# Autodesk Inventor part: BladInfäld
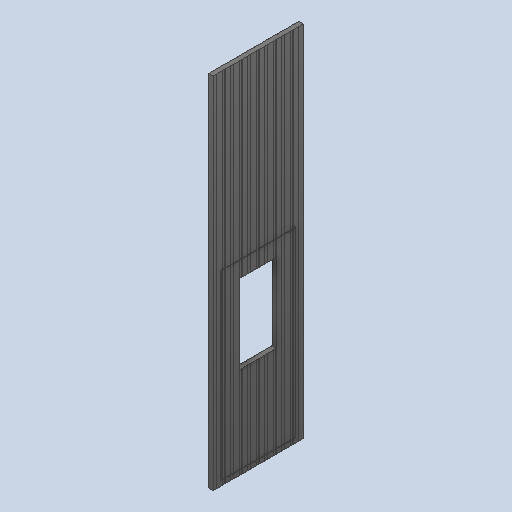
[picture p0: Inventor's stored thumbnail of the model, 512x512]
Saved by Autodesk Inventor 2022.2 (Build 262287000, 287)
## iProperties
Created: 2019-06
Part Number: BladInfäld
Material: UHMW, Black
Document SubType Name: Modeling
Designer: cl
Density: 0.94 g/cm^3
Appearance: Smooth - Black
Author: cl
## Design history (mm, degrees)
sketch "Sketch4"
  geometry: L1 (0, 0)-(0, -35); L2 (0, -35)-(1.4, -36.4); L3 (1.4, -36.4)-(1.4, -96.4); L4 (1.4, -96.4)-(0, -97.8); L5 (0, 0)-(-23.6, 0); L6 (0, -97.8)-(-23.6, -97.8); L7 (-23.6, -97.8)-(-23.6, 0); L8 (-47.2, 0)-(-23.6, 0); L9 (-47.2, 0)-(-47.2, -35); L10 (-47.2, -35)-(-48.6, -36.4); L11 (-48.6, -36.4)-(-48.6, -96.4); L12 (-48.6, -96.4)-(-47.2, -97.8); L13 (-47.2, -97.8)-(-23.6, -97.8); 1 further point
  constraints: 26 end point, 5 symmetric about line, 3 vertical, 2 horizontal, 1 coincident
  dimensions: "d41" = 35 distance of L1.start L1.end; "d43" = 45 deg angle of L2 L1; "d44" = 60 distance of L2.end L3.end; "d45" = 45 deg angle of L3 L4; "d46" = 1.4 distance between parallel lines of L1 L3; "d47" = 1.4 horizontal distance of L3.end L4.end (derived); "d48" = 23.6 distance of L1.start L5.end
extrude "Extrusion2" new body sketch "Sketch4" distance "d49" = 3921 (derived); taper "d50" = 0 deg
sketch "Sketch5"
  geometry: L1 (-48.6, -96.4)-(-47.2, -97.8) reference; L2 (-47.2, -97.8)-(-47.2, -127.8); L3 (-47.2, -97.8)-(-17.2, -97.8); L4 (-47.2, -127.8)-(-48.6, -129.2); L5 (-48.6, -129.2)-(-48.6, -189.2); L6 (-47.2, -97.8)-(-23.6, -97.8); L7 (-47.2, -97.8)-(0, -97.8) reference; L8 (-23.6, -97.8)-(-23.6, -190.6); L9 (-48.6, -189.2)-(-47.2, -190.6); L10 (-47.2, -190.6)-(-23.6, -190.6); L11 (0, -97.8)-(-30, -97.8); L12 (0, -97.8)-(0, -127.8); L13 (0, -127.8)-(1.4, -129.2); L14 (1.4, -129.2)-(1.4, -189.2); L15 (0, -190.6)-(-23.6, -190.6); L16 (1.4, -189.2)-(0, -190.6); 1 further point
  constraints: 28 end point, 5 symmetric about line, 2 horizontal, 2 perpendicular, 2 vertical, 1 midpoint, 1 parallel
  dimensions: "d51" = 30 distance of L1.end L2.end; "d52" = 90 deg angle of L2 L3 (derived); "d54" = 1.4 distance between parallel lines of L2 L5; "d55" = 23.6 distance of L1.end L6.end; "d56" = 45 deg angle of L9 L5; "d57" = 1.4 distance from line of L5 L9.end; "d60" = 60 distance of L4.end L5.end
extrude "Extrusion3" join sketch "Sketch5" distance "d58" = 3921 (derived); taper "d59" = 0 deg
pattern_linear "Rectangular Pattern1" dims "d61" = 85.33405 (derived), "d63" = 92.8
sketch "Sketch7"
  geometry: L1 (-47.2, -189.233)-(0, -189.233); L2 (0, -189.233)-(0, -983.5); L3 (0, -983.5)-(-47.2, -983.5); L4 (-47.2, -983.5)-(-47.2, -189.233); L5 (0, 0)-(-47.2, 0) reference; L6 (-47.2, -97.8)-(-47.2, -127.8) reference; L7 (-47.2, -127.8)-(-48.6, -129.2) reference; L8 (-48.6, -129.2)-(-48.6, -189.2) reference; L9 (-48.6, -189.2)-(-47.2, -190.6) reference; L10 (-47.2, -190.6)-(-47.2, -220.6) reference; L11 (-47.2, -220.6)-(-48.6, -222) reference; L12 (-48.6, -222)-(-48.6, -282) reference; L13 (-48.6, -282)-(-47.2, -283.4) reference; L14 (-47.2, -283.4)-(-47.2, -313.4) reference; L15 (-47.2, -313.4)-(-48.6, -314.8) reference; L16 (-48.6, -314.8)-(-48.6, -374.8) reference; L17 (-48.6, -374.8)-(-47.2, -376.2) reference; L18 (0, -376.2)-(1.4, -374.8) reference; L19 (1.4, -374.8)-(1.4, -314.8) reference; L20 (1.4, -314.8)-(0, -313.4) reference; L21 (0, -313.4)-(0, -283.4) reference; L22 (0, -283.4)-(1.4, -282) reference; L23 (1.4, -282)-(1.4, -222) reference; L24 (1.4, -222)-(0, -220.6) reference; L25 (0, -220.6)-(0, -190.6) reference; L26 (0, -190.6)-(1.4, -189.2) reference; L27 (1.4, -189.2)-(1.4, -129.2) reference; L28 (1.4, -129.2)-(0, -127.8) reference; L29 (0, -127.8)-(0, -97.8) reference; L30 (-47.2, -35)-(-48.6, -36.4) reference; L31 (-48.6, -36.4)-(-48.6, -96.4) reference; L32 (-48.6, -96.4)-(-47.2, -97.8) reference; L33 (0, -97.8)-(1.4, -96.4) reference; L34 (1.4, -96.4)-(1.4, -36.4) reference; L35 (1.4, -36.4)-(0, -35) reference; L36 (0, -35)-(0, 0) reference; L37 (0, 0)-(-47.2, 0) reference; L38 (-47.2, 0)-(-47.2, -35) reference; L39 (-47.2, -376.2)-(-47.2, -406.2) reference; L40 (-47.2, -406.2)-(-48.6, -407.6) reference; L41 (-48.6, -407.6)-(-48.6, -467.6) reference; L42 (-48.6, -467.6)-(-47.2, -469) reference; L43 (-47.2, -469)-(-47.2, -499) reference; L44 (-47.2, -499)-(-48.6, -500.4) reference; L45 (-48.6, -500.4)-(-48.6, -560.4) reference; L46 (-48.6, -560.4)-(-47.2, -561.8) reference; L47 (0, -561.8)-(1.4, -560.4) reference; L48 (1.4, -560.4)-(1.4, -500.4) reference; L49 (1.4, -500.4)-(0, -499) reference; L50 (0, -499)-(0, -469) reference; L51 (0, -469)-(1.4, -467.6) reference; L52 (1.4, -467.6)-(1.4, -407.6) reference; L53 (1.4, -407.6)-(0, -406.2) reference; L54 (0, -406.2)-(0, -376.2) reference; L55 (-47.2, -561.8)-(-47.2, -591.8) reference; L56 (-47.2, -591.8)-(-48.6, -593.2) reference; L57 (-48.6, -593.2)-(-48.6, -653.2) reference; L58 (-48.6, -653.2)-(-47.2, -654.6) reference; L59 (-47.2, -654.6)-(-47.2, -684.6) reference; L60 (-47.2, -684.6)-(-48.6, -686) reference; L61 (-48.6, -686)-(-48.6, -746) reference; L62 (-48.6, -746)-(-47.2, -747.4) reference; L63 (0, -747.4)-(1.4, -746) reference; L64 (1.4, -746)-(1.4, -686) reference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; 2 further points
  constraints: 8 end point, 2 parallel, 2 point on line, 1 horizontal, 1 perpendicular
  dimensions: "d67" = 983.5 distance between parallel lines of L5 L3 (derived); "d103" = 47.2 distance between parallel lines of L2 L4
extrude "Extrusion5" join sketch "Sketch7" distance "d68" = 3921 (derived); taper "d69" = 0 deg
sketch "Sketch10"
  geometry: L1 (195.35, 1862)-(595.35, 1862); L2 (595.35, 1862)-(595.35, 1000); L3 (595.35, 1000)-(195.35, 1000); L4 (195.35, 1000)-(195.35, 1862); L5 (395.35, 1000)-(395.35, 1862); L6 (195.35, 1000)-(595.35, 1000); L7 (595.35, 1000)-(595.35, 1862); L8 (595.35, 1862)-(195.35, 1862); L9 (195.35, 1862)-(195.35, 1000); L10 (395.35, 1862)-(395.35, 1000); 1 further point
  constraints: 20 end point, 4 midpoint, 4 parallel, 2 horizontal, 2 perpendicular, 1 collinear
  dimensions: "d82" = 862 distance of L1.end L2.end (derived); "d83" = 400 distance of L2.end L3.end (derived); "d86" = 491.75 distance from line of L5 point (-96.4, 0) (derived); "d92" = 1000 distance from line of point (-96.4, 0) L3 (derived); "d93" = 400 distance of L6.start L6.end (derived); "d94" = 862 distance of L6.end L7.end (derived); "d95" = 0.0001 distance between parallel lines of L3 L6 (derived)
extrude "Extrusion8" cut sketch "Sketch10" stored distance "d87" = 100; taper "d88" = 0 deg
sketch "Sketch13"
  geometry: L1 (-35, 0)-(-35, 3921) reference; L2 (711, 0)-(712.4, 0) reference; L3 (651, 0)-(711, 0) reference; L4 (649.6, 0)-(651, 0) reference; L5 (619.6, 0)-(649.6, 0) reference; L6 (618.2, 0)-(619.6, 0) reference; L7 (558.2, 0)-(618.2, 0) reference; L8 (556.8, 0)-(558.2, 0) reference; L9 (526.8, 0)-(556.8, 0) reference; L10 (525.4, 0)-(526.8, 0) reference; L11 (465.4, 0)-(525.4, 0) reference; L12 (464, 0)-(465.4, 0) reference; L13 (434, 0)-(464, 0) reference; L14 (432.6, 0)-(434, 0) reference; L15 (372.6, 0)-(432.6, 0) reference; L16 (371.2, 0)-(372.6, 0) reference; L17 (341.2, 0)-(371.2, 0) reference; L18 (339.8, 0)-(341.2, 0) reference; L19 (279.8, 0)-(339.8, 0) reference; L20 (278.4, 0)-(279.8, 0) reference; L21 (248.4, 0)-(278.4, 0) reference; L22 (247, 0)-(248.4, 0) reference; L23 (187, 0)-(247, 0) reference; L24 (185.6, 0)-(187, 0) reference; L25 (155.6, 0)-(185.6, 0) reference; L26 (154.2, 0)-(155.6, 0) reference; L27 (94.2, 0)-(154.2, 0) reference; L28 (92.8, 0)-(94.2, 0) reference; L29 (62.8, 0)-(92.8, 0) reference; L30 (61.4, 0)-(62.8, 0) reference; L31 (1.4, 0)-(61.4, 0) reference; L32 (0, 0)-(1.4, 0) reference; L33 (-35, 0)-(0, 0) reference; L34 (0, 0)-(-35, 0) reference; L35 (1.4, 0)-(0, 0) reference; L36 (61.4, 0)-(1.4, 0) reference; L37 (62.8, 0)-(61.4, 0) reference; L38 (92.8, 0)-(62.8, 0) reference; L39 (94.2, 0)-(92.8, 0) reference; L40 (154.2, 0)-(94.2, 0) reference; L41 (155.6, 0)-(154.2, 0) reference; L42 (185.6, 0)-(155.6, 0) reference; L43 (187, 0)-(185.6, 0) reference; L44 (247, 0)-(187, 0) reference; L45 (248.4, 0)-(247, 0) reference; L46 (278.4, 0)-(248.4, 0) reference; L47 (279.8, 0)-(278.4, 0) reference; L48 (339.8, 0)-(279.8, 0) reference; L49 (341.2, 0)-(339.8, 0) reference; L50 (371.2, 0)-(341.2, 0) reference; L51 (372.6, 0)-(371.2, 0) reference; L52 (432.6, 0)-(372.6, 0) reference; L53 (434, 0)-(432.6, 0) reference; L54 (464, 0)-(434, 0) reference; L55 (465.4, 0)-(464, 0) reference; L56 (525.4, 0)-(465.4, 0) reference; L57 (526.8, 0)-(525.4, 0) reference; L58 (556.8, 0)-(526.8, 0) reference; L59 (558.2, 0)-(556.8, 0) reference; L60 (618.2, 0)-(558.2, 0) reference; L61 (619.6, 0)-(618.2, 0) reference; L62 (649.6, 0)-(619.6, 0) reference; L63 (651, 0)-(649.6, 0) reference; L64 (711, 0)-(651, 0) reference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
  constraints: 16 end point, 4 parallel, 2 perpendicular, 1 horizontal, 3 other
  dimensions: "d96" = 1993 distance of L70.end L71.end; "d97" = 8.5 distance between parallel lines of L73 L77; "d98" = 82 distance between parallel lines of L68 L71; "d99" = 82 distance between parallel lines of L1 L73; "d100" = 49 distance between parallel lines of L46 L72
extrude "Extrusion10" cut sketch "Sketch13" stored distance "d101" = 100; taper "d102" = 0 deg
body "Solid2"
node "Projected Loop1"
node "Projected Loop4"
node "Projected Loop5"
other parameters: "d24" = 45 deg, "BladBredd" = 987.5, "AntalVeck" = 9.88685 (computed from BladBredd) [user parameter], "Fönsterhöjd" = 862, "Blad2" = 1012.5, "Blad3" = 0, "Blad4" = 0, "Blad5" = 1012.5, "Blad6" = 2025, "MGJ12Djup" = 0, "MGJ12Bredd" = 0, "MGJ2Djup" = 0, "MGJ2Bredd" = 5012.5, "MGJ56Djup" = 0, "MGJ56Bredd" = 0, "MGJ23Djup" = 48, "MGJ45Djup" = 48, "GarageRegel5" = 0, "GarageRegel6" = 0, "Styrrulle2Djup" = 0, "FönsterhöjdStyrning" = 862, "FönsterKarm" = 54, "AndraGlasraden" = 0, "BrösthöjdStyrning2" = 0.0001, "InfälldGångDörr" = 0, "Infälldstyr" = 845.83333
